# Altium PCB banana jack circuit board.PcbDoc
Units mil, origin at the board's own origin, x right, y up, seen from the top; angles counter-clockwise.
Board outline 5435 x 1545 mil, 2 copper layers (Top Layer, Bottom Layer); 14 components, 17 nets, 33 pads, 4 vias.
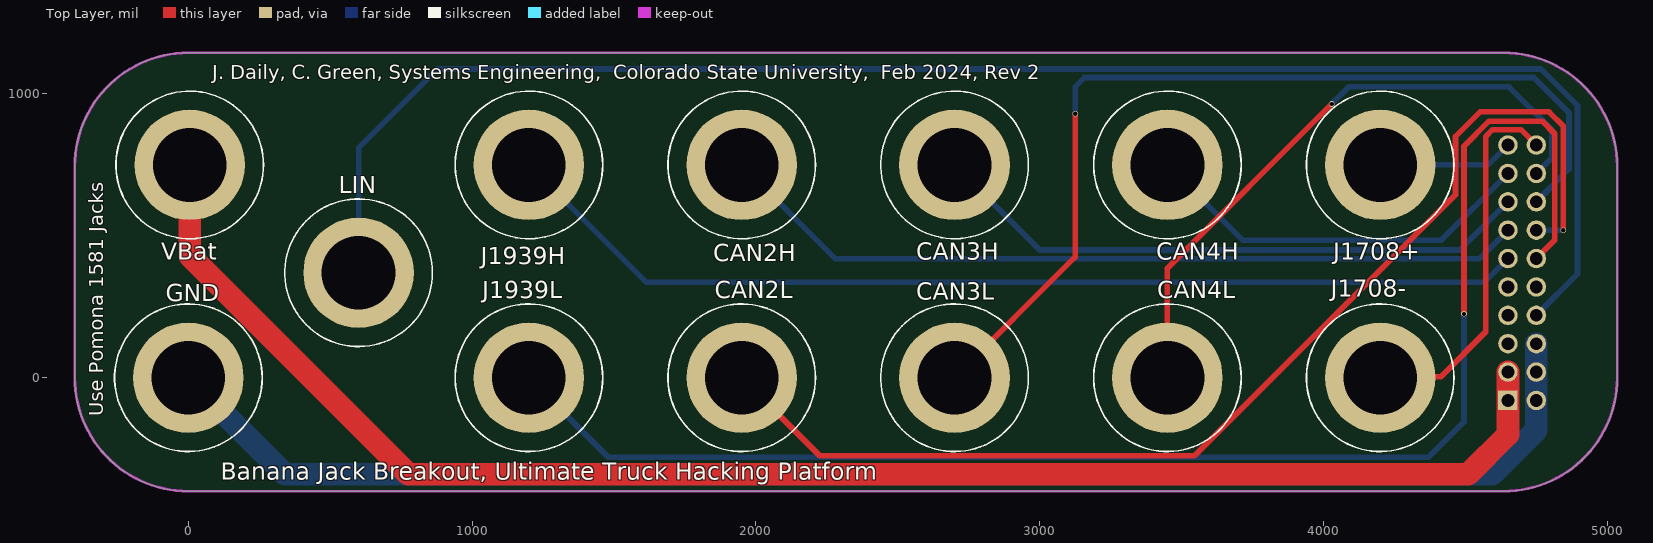
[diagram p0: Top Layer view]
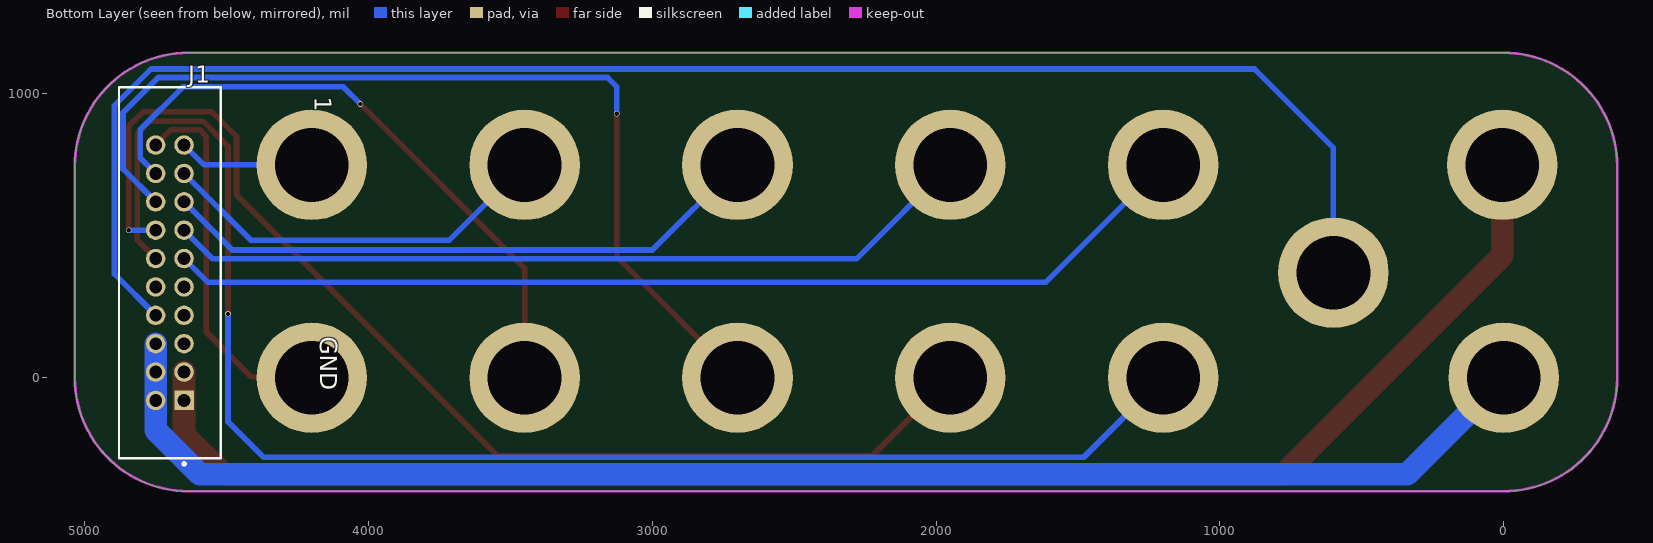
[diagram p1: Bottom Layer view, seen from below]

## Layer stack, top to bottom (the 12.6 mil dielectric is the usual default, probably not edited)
Top Solder: solder mask 0.4, Solder Resist, Dk 3.5
Top Layer: signal copper 1.4
Dielectric 1: dielectric 12.6, FR-4, Dk 4.8
Bottom Layer: signal copper 1.4
Bottom Solder: solder mask 0.4, Solder Resist, Dk 3.5

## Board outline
-400,0 -400,745 cw(c0,745) 0,1145 4635,1145 cw(c4635,745) 5035,745 5035,0 cw(c4635,0) 4635,-400 0,-400 cw(c0,0)

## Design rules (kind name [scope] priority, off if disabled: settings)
Clearance [All] p1: gap=10 ignorepadtopadclearanceinfootprint=FALSE except(0: Arc-Hole Track-Hole SMDPad-Hole THPad-Hole Via-Hole Fill-Hole Poly-Hole Region-Hole Text-Hole)
PolygonConnect [All] p1: connectstyle=Relief reliefconductorwidth=10 reliefentries=4 polygonreliefangle="90 Angle" airgapwidth=10
RoutingVias [All] p1: holewidth=15 width=20 viastyle="Through Hole" minholewidth=15 minwidth=20 maxholewidth=19 maxwidth=100
SMDNeckDown [All] p1: percent=50.000
SolderMaskExpansion [All] p1: expansion=4 istentingtop=FALSE
Width Width_3 [All] p1: maxlimit=100 minlimit=20 preferedwidth=20 minimp=50.000000 maximp=50.000000 favimp=50.000000
30 further rules are at their usual default settings.

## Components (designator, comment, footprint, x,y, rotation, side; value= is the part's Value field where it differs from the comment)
CAN2H "1581-5" FP-1581-5-MFG 3450,750 r0 top
CAN2L "1581-5" FP-1581-5-MFG 3450,0 r0 top
CAN3H "1581-5" FP-1581-5-MFG 2700,750 r0 top
CAN3L "1581-5" FP-1581-5-MFG 2700,0 r0 top
CAN4H "1581-5" FP-1581-5-MFG 1950,750 r0 top
CAN4L "1581-5" FP-1581-5-MFG 1950,0 r0 top
GND "1581-5" FP-1581-5-MFG 0,0 r0 top
J1 "70246-2001" FP-70246-2001-MFG 4700,370 r90 bottom
J1708+ "1581-5" FP-1581-5-MFG 1200,750 r0 top
J1708- "1581-5" FP-1581-5-MFG 1200,0 r0 top
J1939H "1581-5" FP-1581-5-MFG 4200,750 r0 top
J1939L "1581-5" FP-1581-5-MFG 4200,0 r0 top
LIN "1581-5" FP-1581-5-MFG 600,370 r0 top
VBat "1581-5" FP-1581-5-MFG 5,750 r0 top

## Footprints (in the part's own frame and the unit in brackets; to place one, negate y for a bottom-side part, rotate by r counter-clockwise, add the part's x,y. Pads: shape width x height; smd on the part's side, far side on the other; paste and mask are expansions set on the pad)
FP-1581-5-MFG [mm]
  round 9.9 hole 6.6 paste-2539.97 mask+0: 1(0,0)
  silkscreen extent -6.6,-6.6 6.6,6.6, body extent -6.7,-6.7 6.7,6.7, height 0.25
FP-70246-2001-MFG [mm]
  rect 1.74x1.74 hole 1.14 paste-2539.97 mask+0: 1(-11.43,-1.27)
  round 1.74 hole 1.14 paste-2539.97 mask+0: 2(-11.43,1.27) 3(-8.89,-1.27) 4(-8.89,1.27) 5(-6.35,-1.27) 6(-6.35,1.27) 7(-3.81,-1.27) 8(-3.81,1.27) 9(-1.27,-1.27) 10(-1.27,1.27) 11(1.27,-1.27) 12(1.27,1.27) 13(3.81,-1.27) 14(3.81,1.27) 15(6.35,-1.27) 16(6.35,1.27) 17(8.89,-1.27) 18(8.89,1.27) 19(11.43,-1.27) 20(11.43,1.27)
  silkscreen extent -17.23,-4.55 16.61,4.54, body extent -16.51,-4.45 16.51,4.45, height 9.47

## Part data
CAN2H CAN2L CAN3H CAN3L CAN4H CAN4L GND J1708+ J1708- J1939H J1939L LIN VBat: library part CMP-73906-000011-1, "CONN BANANA JACK TURRET GREEN", Color=Green, Current Rating=15A, Package Quantity=1, Voltage Rating=2.5kV, Voltage Rating (AC)=30V, Voltage Rating (DC)=60V
J1: library part CMP-04776-001013-1, "CONN HEADER VERT 20POS 2.54MM", Color=Black, Contact Resistance=15mR, Current Rating=2.5A, Flammability Rating="UL94 V-0", Insulation Resistance=12GR, Max Operating Temperature=120°C, Max Voltage Rating (AC)=250V, Min Operating Temperature=-55°C, Package Quantity=720

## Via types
v1: diameter 20, hole 15, Top Layer to Bottom Layer, 4 vias

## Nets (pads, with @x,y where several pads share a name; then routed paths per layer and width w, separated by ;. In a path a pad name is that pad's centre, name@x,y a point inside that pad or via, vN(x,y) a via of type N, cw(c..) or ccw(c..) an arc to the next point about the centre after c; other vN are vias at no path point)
5V0: J1.5
GND: GND.1 J1.2 J1.4 J1.6 | length 5260
  Bottom Layer w80: GND.1 340,-340 4595,-340 4750,-185 J1.2 J1.4 J1.6
NetCAN2H_1: CAN2H.1 J1.17 | length 1407.1
  Bottom Layer w20: CAN2H.1 3715,485 4415,485 J1.17
NetCAN2L_1: CAN2L.1 J1.18 | length 2244.1
  Top Layer w20: CAN2L.1 3450,386 v1(4028.88,964.88)
  Bottom Layer w20: v1(4028.88,964.88) 4089,1025 4653.5,1025 4804.25,874.25 4804.25,774.25 J1.18
NetCAN3H_1: CAN3H.1 J1.15 | length 2144.7
  Bottom Layer w20: CAN3H.1 3000,450 4480,450 J1.15
NetCAN3L_1: CAN3L.1 J1.16 | length 3367.7
  Top Layer w20: CAN3L.1 3125,425 v1(3125,930)
  Bottom Layer w20: v1(3125,930) 3125,1025 3158,1058 4741,1058 4865,934 4865,735 J1.16
NetCAN4H_1: CAN4H.1 J1.13 | length 2878.9
  Bottom Layer w20: CAN4H.1 2281,419 4549,419 J1.13
NetCAN4L_1: CAN4L.1 J1.14 | length 4113.7
  Top Layer w20: CAN4L.1 2225,-275 3545,-275 4465,645 4465,850 4552,937 4795,937 4845,887 v1(4845,520)
  Bottom Layer w20: J1.14 v1(4845,520)
NetJ1_7: J1.7
NetJ1_8: J1.8 LIN.1 | length 5702.6
  Bottom Layer w20: LIN.1 600,810 878,1088 4766,1088 4895,959 4895,365 J1.8
NetJ1_9: J1.9
NetJ1_10: J1.10
NetJ1_11: J1.11 J1708+.1 | length 3656.3
  Bottom Layer w20: J1708+.1 1614,336 4566,336 J1.11
NetJ1_12: J1.12 J1708-.1 | length 5275.4
  Top Layer w20: v1(4495,225) 4495,815.68 4583.57,904.25 4770.75,904.25 4815,860 4815,485 J1.12
  Bottom Layer w20: J1708-.1 1480,-280 4370,-280 4495,-155 v1(4495,225)
NetJ1_19: J1.19 J1939H.1 | length 479
  Bottom Layer w20: J1939H.1 4580,750 J1.19
NetJ1_20: J1.20 J1939L.1 | length 1337.8
  Top Layer w20: J1939L.1 4203.17,3.17 4413.17,3.17 4572,162 4572,850.25 4596,874.25 4695.75,874.25 J1.20
RAW: J1.1 J1.3 VBat.1 | length 5561.9
  Top Layer w80: VBat.1 5,430 775,-340 4510,-340 4650,-200 J1.1 J1.3

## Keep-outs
Keep-Out Layer:
  the board outline again, w10

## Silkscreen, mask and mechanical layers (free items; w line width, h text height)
Top Overlay:
  text "J. Daily, C. Green, Systems Engineering,  Colorado State University,  Feb 2024, Rev 2" at 85,1051.66 h50
  text "Use Pomona 1581 Jacks" at -300,-135 h50 r90
  text "Banana Jack Breakout, Ultimate Truck Hacking Platform" at 115,-360.01 h60
Bottom Overlay:
  text "1" at 4190,990 h60 r90
  text "GND" at 4170,145 h60 r90

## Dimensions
1950,750 to 1200,750 on Mechanical 1
2700,750 to 1950,750 on Mechanical 1
3450,750 to 2700,750 on Mechanical 1
3450,750 to 4200,750 on Mechanical 1
600,370 to 5,750 on Mechanical 1
0,0 to 600,370 on Mechanical 1
4200,0 to 4200,750 on Mechanical 1
3450,0 to 4200,0 on Mechanical 1
2700,0 to 3450,0 on Mechanical 1
1950,0 to 2700,0 on Mechanical 1
1200,0 to 1950,0 on Mechanical 1
0,0 to 1200,0 on Mechanical 1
